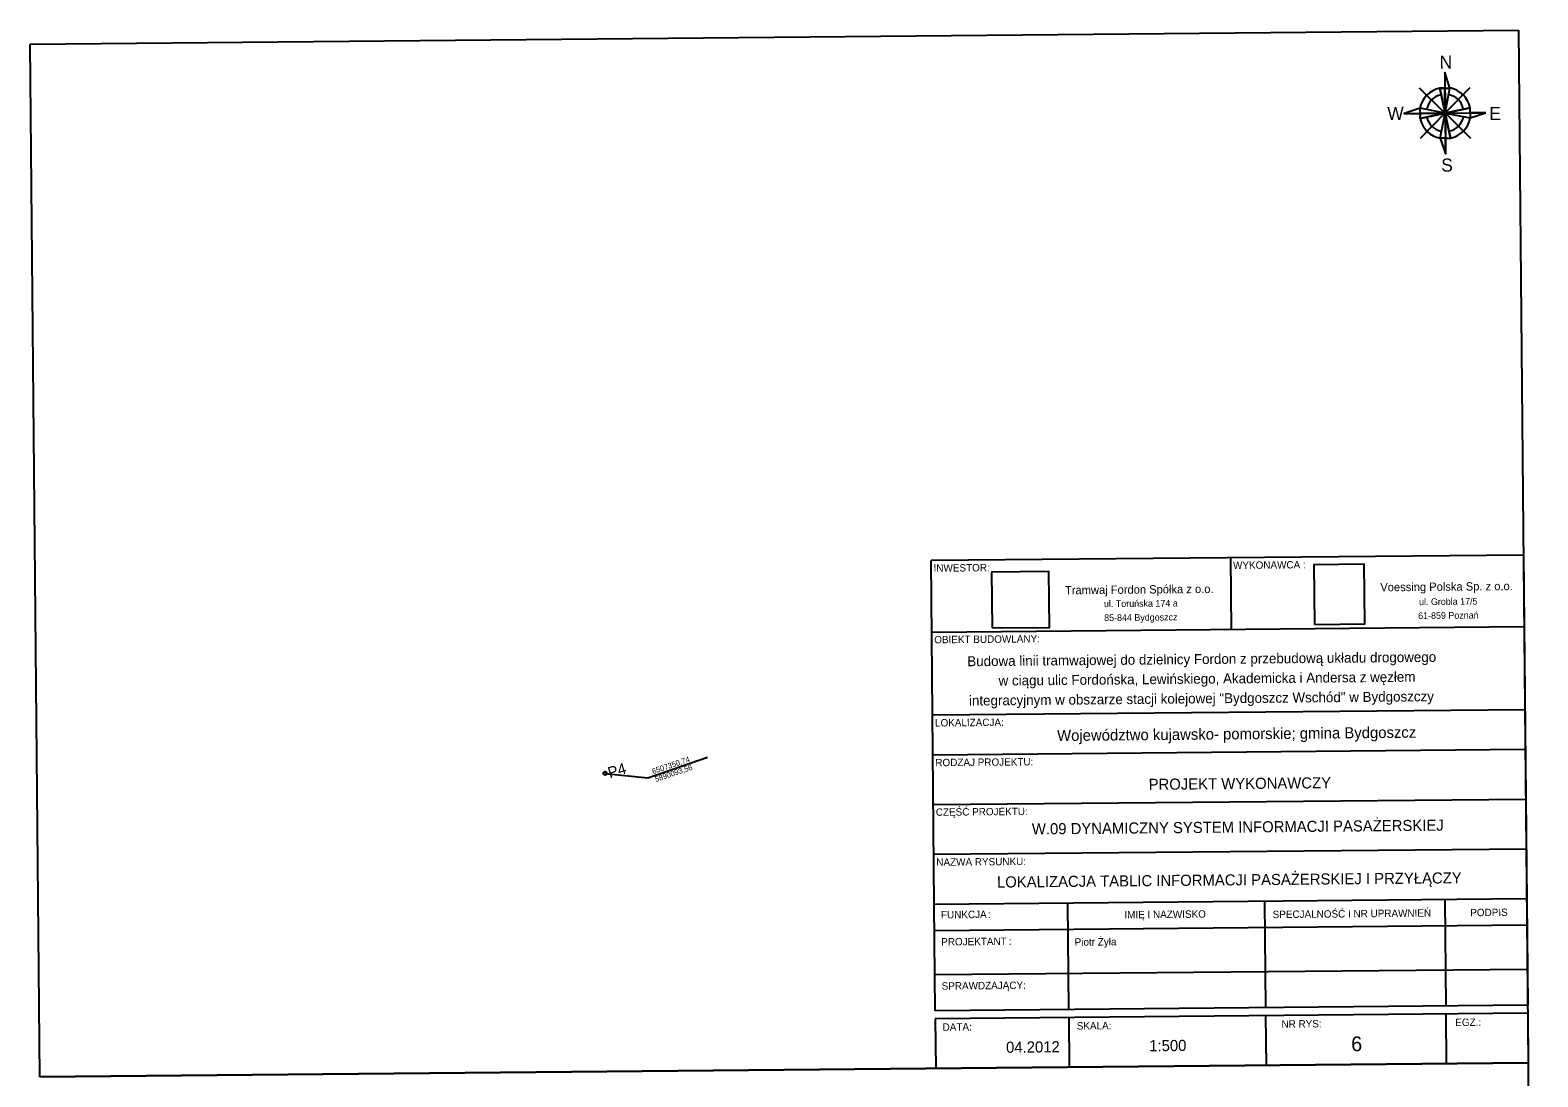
# Model space of a CAD drawing. Extents: x 6505045 to 6511721, y 5887996 to 5893535.
# Drawn here: x 6507273.1 to 6507476.7, y 5890052.6 to 5890193.9 of the extents above; entities that cross this region are included whole.
import ezdxf

# ---------------------------------------------------------------- set-up
doc = ezdxf.new("R2010")
doc.units = 0
for name, color, linetype in [('__legenda', 7, 'Continuous'), ('Default', 7, 'Continuous'), ('P_opisy', 7, 'Continuous'), ('P_przylacze', 7, 'Continuous'), ('P_tabela', 7, 'Continuous'), ('P_wsporzedne', 7, 'Continuous'), ('P_znak północy', 7, 'Continuous'), ('SA_Linie-020', 7, 'Continuous'), ('SA_Stempel_Text-020', 7, 'Continuous'), ('SA_Stempel_Text-030', 7, 'Continuous'), ('SA_Stempel_Text-035', 7, 'Continuous'), ('SA_Unterschrift_Text', 7, 'Continuous')]:
    doc.layers.add(name, color=color, linetype=linetype)

msp = doc.modelspace()

# ---------------------------------------------------------------- linework, layer by layer
at = {"layer": '__legenda'}
msp.add_lwpolyline([(6507446.54, 5890113.66), (6507453.34, 5890113.73), (6507453.26, 5890121.79), (6507446.46, 5890121.73)], close=True, dxfattribs=at)
at = {"layer": 'Default'}
msp.add_lwpolyline([(6507403.01, 5890113.19), (6507410.75, 5890113.26), (6507410.68, 5890120.8), (6507402.94, 5890120.73)], close=True, dxfattribs=at)
at = {"layer": 'P_przylacze'}
msp.add_circle((6507350.74, 5890093.56), 0.25, dxfattribs=at)
msp.add_circle((6507350.74, 5890093.56), 0.25, dxfattribs=at)
at = {"layer": 'P_tabela'}
for p, q in [((6507273.11, 5890192.03), (6507474.1, 5890193.9)), ((6507274.41, 5890052.58), (6507273.11, 5890192.03)), ((6507474.1, 5890193.9), (6507475.4, 5890054.46)), ((6507274.41, 5890052.58), (6507475.4, 5890054.46)), ((6507475.4, 5890054.46), (6507274.41, 5890052.58)), ((6507475.4, 5890054.46), (6507476.7, 5889915.01))]:
    msp.add_line(p, q, dxfattribs=at)
at = {"layer": 'P_wsporzedne'}
for p, q in [((6507356.5, 5890092.94), (6507364.58, 5890095.73)), ((6507356.5, 5890092.94), (6507364.58, 5890095.73)), ((6507350.74, 5890093.56), (6507356.5, 5890092.94)), ((6507350.74, 5890093.56), (6507356.5, 5890092.94))]:
    msp.add_line(p, q, dxfattribs=at)
at = {"layer": 'P_znak północy'}
for p, q in [((6507464.12, 5890188.23), (6507464.23, 5890177.19)), ((6507464.12, 5890188.23), (6507464.23, 5890177.19)), ((6507464.16, 5890182.71), (6507460.73, 5890186.09)), ((6507464.16, 5890182.71), (6507460.73, 5890186.09)), ((6507463.45, 5890186.08), (6507464.14, 5890186.08)), ((6507464.17, 5890182.71), (6507463.45, 5890186.08)), ((6507463.45, 5890186.08), (6507464.14, 5890186.08)), ((6507464.17, 5890182.71), (6507463.45, 5890186.08)), ((6507464.14, 5890186.08), (6507464.83, 5890186.09)), ((6507464.14, 5890186.08), (6507464.83, 5890186.09)), ((6507464.17, 5890182.72), (6507467.56, 5890186.15)), ((6507464.17, 5890182.72), (6507467.56, 5890186.15)), ((6507464.17, 5890182.71), (6507464.83, 5890186.09)), ((6507464.17, 5890182.71), (6507464.83, 5890186.09)), ((6507458.65, 5890182.65), (6507469.69, 5890182.76)), ((6507458.65, 5890182.65), (6507469.69, 5890182.76)), ((6507464.17, 5890182.71), (6507460.79, 5890183.36)), ((6507464.17, 5890182.71), (6507460.79, 5890183.36)), ((6507464.17, 5890182.72), (6507460.79, 5890179.26)), ((6507464.17, 5890182.72), (6507460.79, 5890179.26)), ((6507460.8, 5890181.98), (6507464.17, 5890182.71)), ((6507460.8, 5890182.67), (6507464.16, 5890182.71)), ((6507464.16, 5890182.71), (6507460.8, 5890181.98)), ((6507460.8, 5890181.98), (6507464.17, 5890182.71)), ((6507460.8, 5890182.67), (6507464.16, 5890182.71)), ((6507464.16, 5890182.71), (6507460.8, 5890181.98)), ((6507460.8, 5890181.98), (6507460.8, 5890182.67)), ((6507460.8, 5890181.98), (6507460.8, 5890182.67)), ((6507463.52, 5890179.32), (6507464.17, 5890182.71)), ((6507463.52, 5890179.32), (6507464.17, 5890182.71)), ((6507464.17, 5890182.71), (6507467.55, 5890183.43)), ((6507464.17, 5890182.71), (6507467.55, 5890183.43)), ((6507464.17, 5890182.72), (6507467.62, 5890179.32)), ((6507464.17, 5890182.72), (6507467.62, 5890179.32)), ((6507464.17, 5890182.71), (6507467.56, 5890182.05)), ((6507464.17, 5890182.71), (6507464.9, 5890179.33)), ((6507464.17, 5890182.71), (6507467.56, 5890182.05)), ((6507464.17, 5890182.71), (6507464.9, 5890179.33))]:
    msp.add_line(p, q, dxfattribs=at)
for points in [[(6507464.12, 5890188.23), (6507464.14, 5890186.08), (6507464.14, 5890186.08), (6507464.83, 5890186.09), (6507464.12, 5890188.23)], [(6507464.12, 5890188.23), (6507464.14, 5890186.08), (6507464.14, 5890186.08), (6507464.83, 5890186.09), (6507464.12, 5890188.23)], [(6507464.17, 5890182.72), (6507464.14, 5890186.08), (6507463.45, 5890186.08), (6507464.17, 5890182.71), (6507464.17, 5890182.72)], [(6507464.17, 5890182.72), (6507464.14, 5890186.08), (6507463.45, 5890186.08), (6507464.17, 5890182.71), (6507464.17, 5890182.72)], [(6507460.8, 5890182.67), (6507460.79, 5890183.36), (6507458.65, 5890182.65), (6507460.8, 5890182.67)], [(6507460.8, 5890182.67), (6507460.79, 5890183.36), (6507458.65, 5890182.65), (6507460.8, 5890182.67)], [(6507464.16, 5890182.71), (6507460.8, 5890182.67), (6507460.8, 5890181.98), (6507464.16, 5890182.71)], [(6507464.16, 5890182.71), (6507460.8, 5890182.67), (6507460.8, 5890181.98), (6507464.16, 5890182.71)], [(6507464.17, 5890182.71), (6507464.17, 5890182.71), (6507464.18, 5890182.71), (6507467.55, 5890182.74), (6507467.55, 5890183.43), (6507464.17, 5890182.71)], [(6507464.17, 5890182.71), (6507464.17, 5890182.71), (6507464.18, 5890182.71), (6507467.55, 5890182.74), (6507467.55, 5890183.43), (6507464.17, 5890182.71)], [(6507464.21, 5890179.33), (6507464.9, 5890179.33), (6507464.18, 5890182.7), (6507464.21, 5890179.33)], [(6507464.21, 5890179.33), (6507464.9, 5890179.33), (6507464.18, 5890182.7), (6507464.21, 5890179.33)], [(6507469.69, 5890182.76), (6507467.55, 5890182.74), (6507467.56, 5890182.05), (6507469.69, 5890182.76)], [(6507469.69, 5890182.76), (6507467.55, 5890182.74), (6507467.56, 5890182.05), (6507469.69, 5890182.76)], [(6507464.21, 5890179.33), (6507463.52, 5890179.32), (6507464.23, 5890177.19), (6507464.21, 5890179.33)], [(6507464.21, 5890179.33), (6507463.52, 5890179.32), (6507464.23, 5890177.19), (6507464.21, 5890179.33)]]:
    msp.add_lwpolyline(points, dxfattribs=at)
for centre, radius, start, end in [((6507464.17, 5890182.71), 3.45, 102.0474, 168.9738), ((6507464.17, 5890182.71), 3.45, 102.0474, 168.9738), ((6507464.18, 5890182.71), 3.45, 12.0554, 79.0163), ((6507464.18, 5890182.71), 3.45, 12.0554, 79.0163), ((6507464.17, 5890182.72), 2.53, 102.1671, 169.2958), ((6507464.17, 5890182.72), 2.53, 102.1671, 169.2958), ((6507464.17, 5890182.72), 2.53, 11.7816, 78.9353), ((6507464.17, 5890182.72), 2.53, 11.7816, 78.9353), ((6507464.17, 5890182.7), 3.45, 192.0538, 259.0158), ((6507464.17, 5890182.7), 3.45, 192.0538, 259.0158), ((6507464.17, 5890182.72), 2.53, 192.3917, 259.0318), ((6507464.17, 5890182.72), 2.53, 192.3917, 259.0318), ((6507464.17, 5890182.72), 2.53, 282.0081, 348.6723), ((6507464.17, 5890182.72), 2.53, 282.0081, 348.6723), ((6507464.18, 5890182.7), 3.45, 282.0538, 349.0163), ((6507464.18, 5890182.7), 3.45, 282.0538, 349.0163)]:
    msp.add_arc(centre, radius, start, end, dxfattribs=at)
at = {"layer": 'SA_Linie-020'}
for p, q in [((6507474.76, 5890123.03), (6507394.76, 5890122.28)), ((6507474.76, 5890123.03), (6507475.33, 5890062.24)), ((6507395.19, 5890075.86), (6507394.76, 5890122.28)), ((6507435.21, 5890122.66), (6507435.3, 5890113)), ((6507394.85, 5890112.62), (6507474.85, 5890113.37)), ((6507474.95, 5890102.14), (6507394.96, 5890101.4)), ((6507475, 5890096.77), (6507395.01, 5890096.02)), ((6507475.07, 5890090.05), (6507395.07, 5890089.3)), ((6507475.07, 5890090.05), (6507395.07, 5890089.3)), ((6507475.13, 5890083.33), (6507395.13, 5890082.58)), ((6507475.19, 5890076.61), (6507395.19, 5890075.86)), ((6507413.35, 5890061.66), (6507413.22, 5890076.03)), ((6507439.79, 5890076.28), (6507439.92, 5890061.91)), ((6507464.13, 5890076.51), (6507464.26, 5890062.13)), ((6507395.33, 5890061.49), (6507395.19, 5890075.86)), ((6507475.22, 5890073.05), (6507395.23, 5890072.3)), ((6507475.28, 5890067.09), (6507395.28, 5890066.34)), ((6507475.33, 5890062.24), (6507395.33, 5890061.49)), ((6507475.34, 5890061.18), (6507395.34, 5890060.43)), ((6507395.34, 5890060.43), (6507395.4, 5890053.71)), ((6507413.36, 5890060.6), (6507413.42, 5890053.88)), ((6507439.93, 5890060.85), (6507440, 5890054.13)), ((6507464.27, 5890061.07), (6507464.33, 5890054.35)), ((6507475.34, 5890061.18), (6507475.4, 5890054.46)), ((6507475.4, 5890054.46), (6507395.4, 5890053.71))]:
    msp.add_line(p, q, dxfattribs=at)

# ---------------------------------------------------------------- texts
at = {"layer": 'P_opisy'}
msp.add_text('P4', height=1.501, rotation=16.5833, dxfattribs=at).set_placement((6507351.38, 5890092.88))
msp.add_text('P4', height=1.501, rotation=16.5833, dxfattribs=at).set_placement((6507351.38, 5890092.88))
at = {"layer": 'P_wsporzedne'}
for s, p in [('6507350,74', (6507357.24, 5890093.45)), ('6507350,74', (6507357.24, 5890093.45)), ('5890093,56', (6507357.6, 5890092.38)), ('5890093,56', (6507357.6, 5890092.38))]:
    msp.add_text(s, height=0.751, rotation=18.6683, dxfattribs=at).set_placement(p)
at = {"layer": 'P_znak północy'}
for s, p in [('N', (6507463.44, 5890188.71)), ('N', (6507463.44, 5890188.71)), ('W', (6507456.38, 5890181.78)), ('W', (6507456.38, 5890181.78)), ('E', (6507470.15, 5890181.76)), ('E', (6507470.15, 5890181.76)), ('S', (6507463.66, 5890174.8)), ('S', (6507463.66, 5890174.8))]:
    msp.add_text(s, height=1.76, rotation=0.535, dxfattribs=at).set_placement(p)
at = {"layer": 'SA_Stempel_Text-020'}
for s, p in [('INWESTOR:', (6507395.11, 5890120.77)), ('WYKONAWCA :', (6507435.55, 5890121.15)), ('OBIEKT BUDOWLANY:', (6507395.2, 5890111.11)), ('LOKALIZACJA:', (6507395.3, 5890099.88)), ('RODZAJ PROJEKTU:', (6507395.35, 5890094.51)), ('CZĘŚĆ PROJEKTU:', (6507395.41, 5890087.82)), ('NAZWA RYSUNKU:', (6507395.48, 5890081.07)), ('FUNKCJA', (6507396.11, 5890073.97)), (':', (6507402.44, 5890074.03)), ('IMIĘ I NAZWISKO', (6507420.88, 5890073.97)), ('SPECJALNOŚĆ I NR UPRAWNIEŃ', (6507440.89, 5890074.01)), ('PODPIS', (6507467.58, 5890074.26)), ('PROJEKTANT', (6507396.14, 5890070.31)), (':', (6507405.27, 5890070.4)), ('SPRAWDZAJĄCY:', (6507396.2, 5890064.35)), ('DATA:', (6507396.33, 5890058.8)), ('SKALA:', (6507414.44, 5890058.96)), ('NR RYS:', (6507442.09, 5890059.21)), ('EGZ.:', (6507465.55, 5890059.43))]:
    msp.add_text(s, height=1, rotation=0.535, dxfattribs=at).set_placement(p)
at = {"layer": 'SA_Stempel_Text-030'}
for s, height, p in [('1:500', 1.5, (6507424.23, 5890056.03)), ('6', 2, (6507451.5, 5890056.03)), ('04.2012', 1.5, (6507404.9, 5890055.83))]:
    msp.add_text(s, height=height, rotation=0.535, dxfattribs=at).set_placement(p)
at = {"layer": 'SA_Stempel_Text-035'}
for s, height, p in [('Budowa linii tramwajowej do dzielnicy Fordon z przebudową układu drogowego', 1.35, (6507399.66, 5890108.02)), ('w ciągu ulic Fordońska, Lewińskiego, Akademicka i Andersa z węzłem', 1.35, (6507403.89, 5890105.41)), ('integracyjnym w obszarze stacji kolejowej "Bydgoszcz Wschód" w Bydgoszczy', 1.35, (6507399.89, 5890102.71)), ('Województwo kujawsko- pomorskie; gmina Bydgoszcz', 1.5, (6507411.79, 5890097.92)), ('PROJEKT WYKONAWCZY', 1.5, (6507424.15, 5890091.32)), ('W.09 DYNAMICZNY SYSTEM INFORMACJI PASAŻERSKIEJ', 1.5, (6507408.38, 5890085.3)), ('LOKALIZACJA TABLIC INFORMACJI PASAŻERSKIEJ I PRZYŁĄCZY', 1.5, (6507403.67, 5890078.13))]:
    msp.add_text(s, height=height, rotation=0.535, dxfattribs=at).set_placement(p)
at = {"layer": 'SA_Unterschrift_Text'}
for s, height, p in [('Tramwaj Fordon Spółka z o.o.', 1.125, (6507412.85, 5890117.73)), ('Voessing Polska Sp. z o.o.', 1.125, (6507455.43, 5890118.13)), ('ul. Toruńska 174 a', 0.9, (6507418.11, 5890116)), ('ul. Grobla 17/5', 0.9, (6507460.66, 5890116.27)), ('85-844 Bydgoszcz', 0.9, (6507418.14, 5890114.12)), ('61-859 Poznań', 0.9, (6507460.54, 5890114.39)), ('Piotr Żyła', 1, (6507414.16, 5890070.28))]:
    msp.add_text(s, height=height, rotation=0.535, dxfattribs=at).set_placement(p)

doc.saveas('drawing.dxf')
